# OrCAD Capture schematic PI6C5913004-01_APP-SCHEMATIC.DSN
size B; title: PI6C5913004-01 Application Schematic; rev: 1.0; note: Diodes Inc. Clock IC Application Engineering
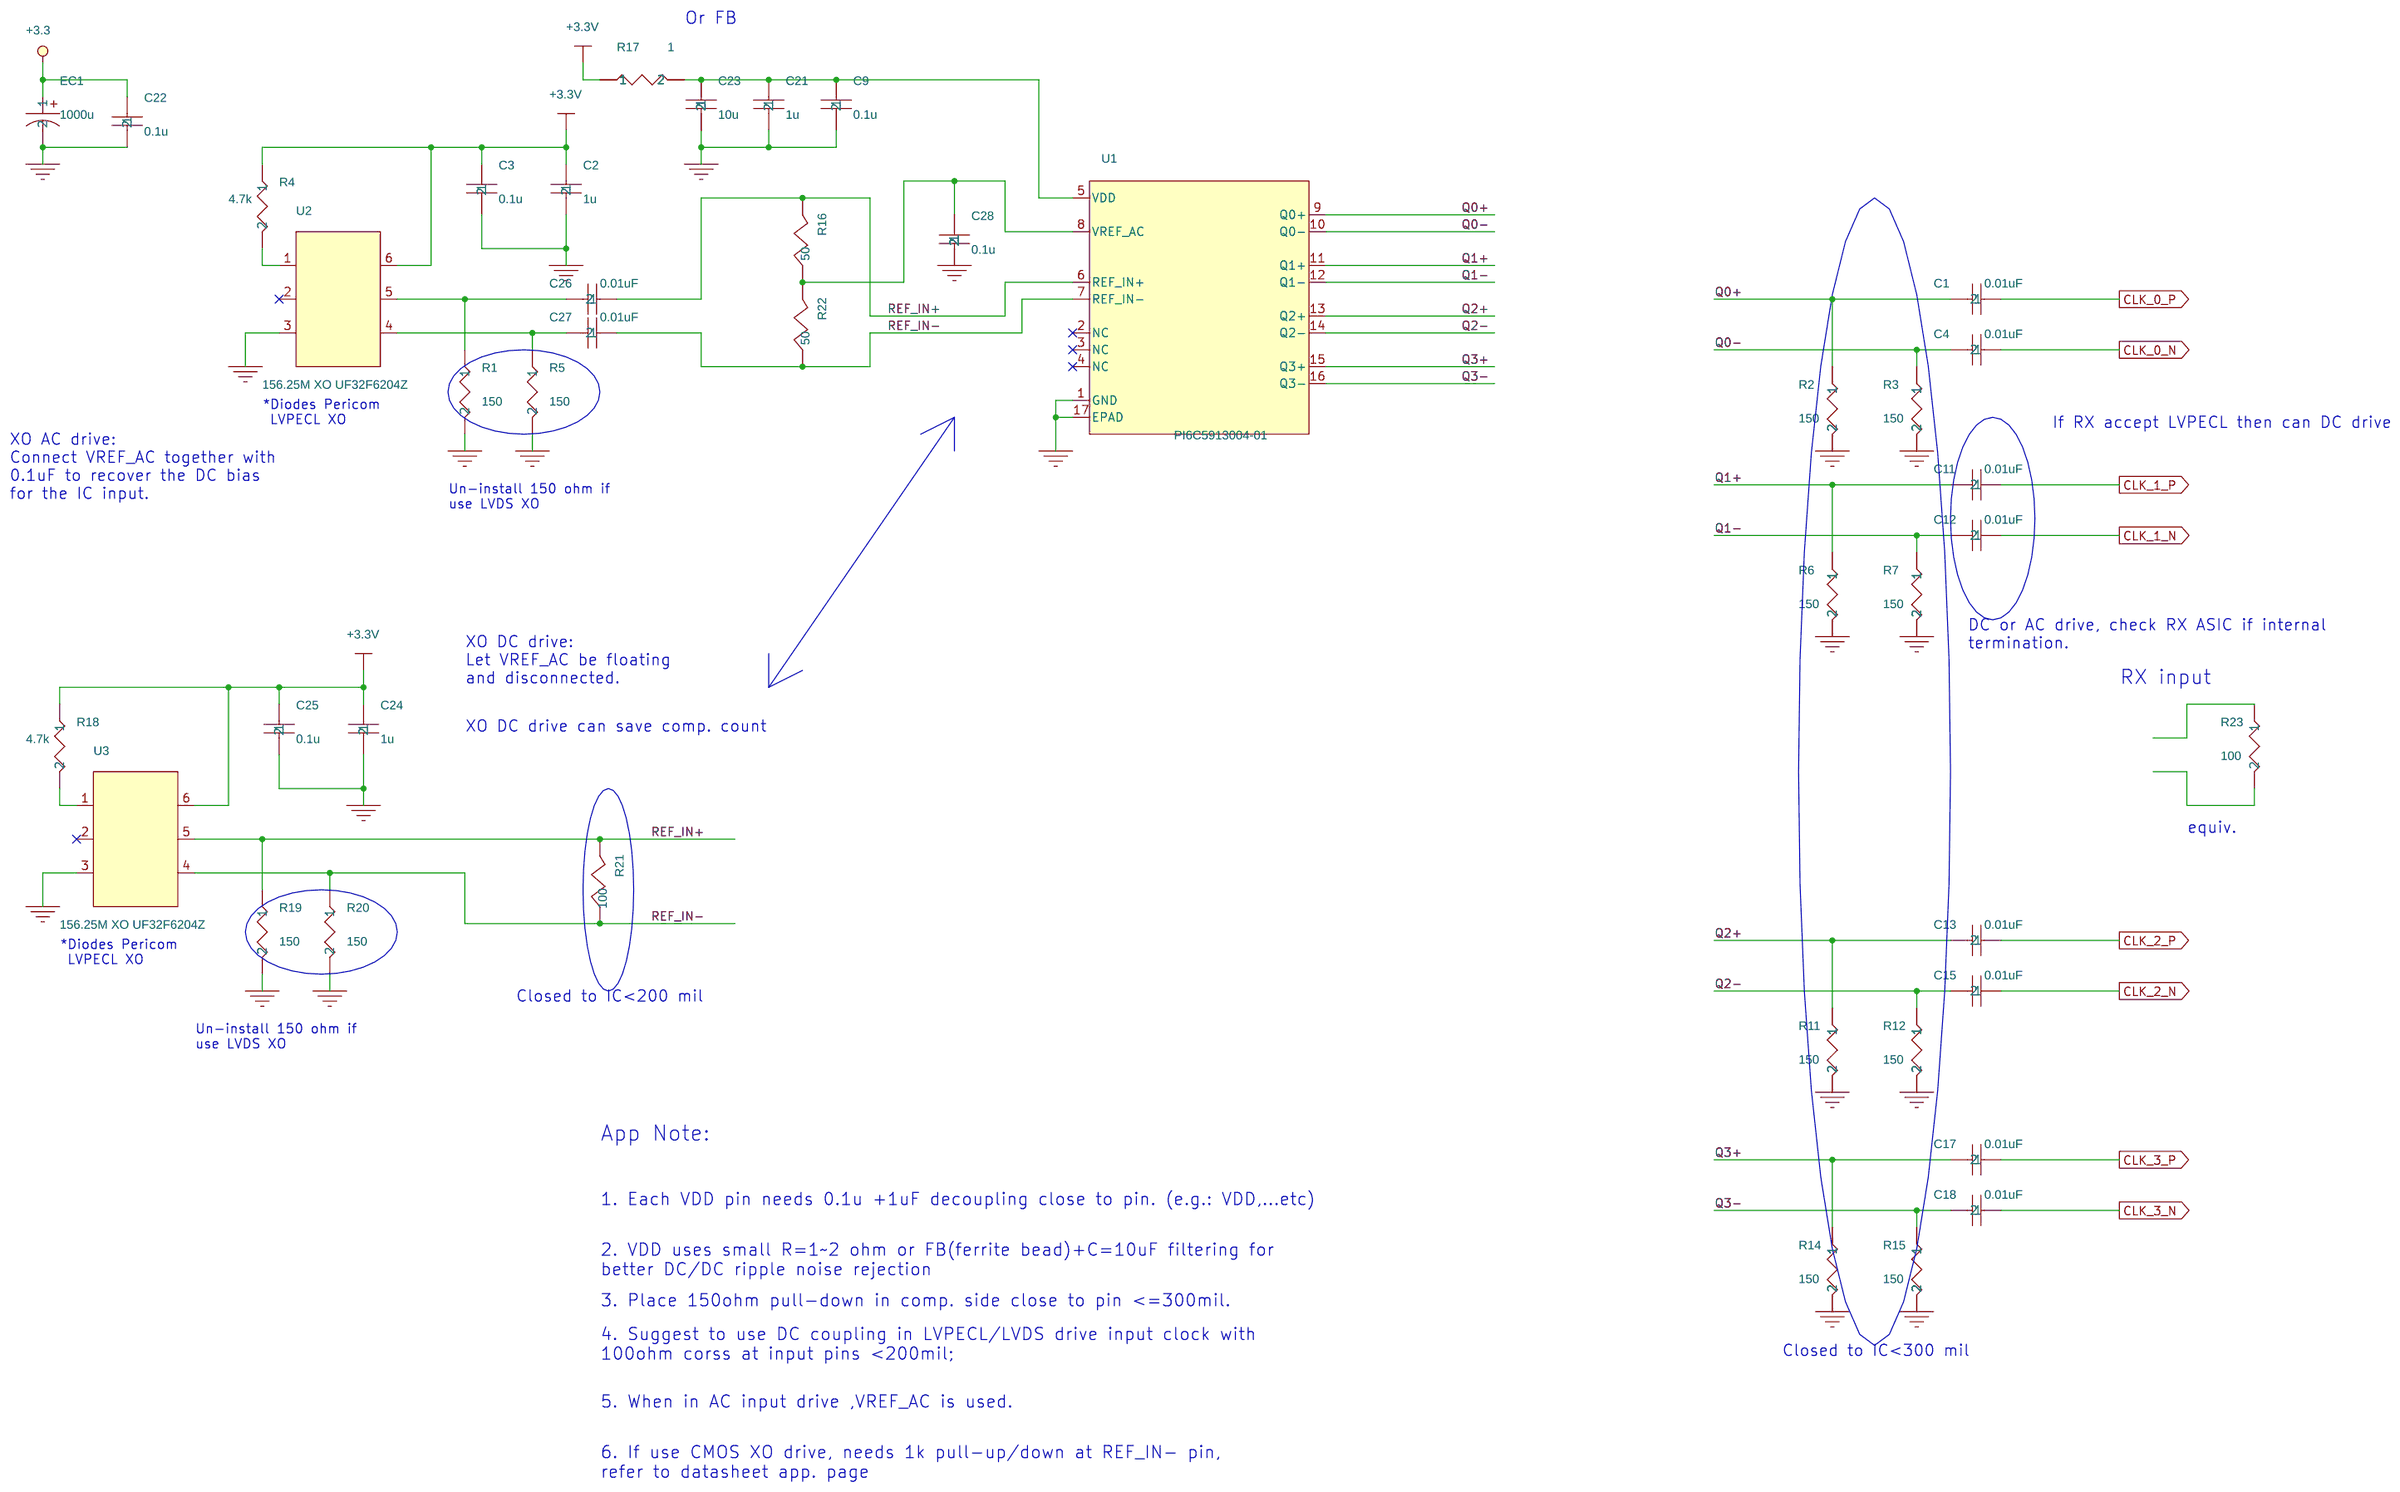
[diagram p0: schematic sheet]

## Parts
C1  0.01uF  [CC_0402]
C2  1u  [CC_0402]
C3  0.1u  [CC_0402]
C4  0.01uF  [CC_0402]
C9  0.1u  [CC_0402]
C11  0.01uF  [CC_0402]
C12  0.01uF  [CC_0402]
C13  0.01uF  [CC_0402]
C15  0.01uF  [CC_0402]
C17  0.01uF  [CC_0402]
C18  0.01uF  [CC_0402]
C21  1u  [CC_0805]
C22  0.1u  [CC_0402]
C23  10u  [CC_0805]
C24  1u  [CC_0402]
C25  0.1u  [CC_0402]
C26  0.01uF  [CC_0402]
C27  0.01uF  [CC_0402]
C28  0.1u  [CC_0402]
EC1  1000u  [CAP1000UF]
R1  150  [R_0402]
R2  150  [R_0402]
R3  150  [R_0402]
R4  4.7k  [R_0402]
R5  150  [R_0402]
R6  150  [R_0402]
R7  150  [R_0402]
R11  150  [R_0402]
R12  150  [R_0402]
R14  150  [R_0402]
R15  150  [R_0402]
R16  50
R17  1  [R_0402]
R18  4.7k  [R_0402]
R19  150  [R_0402]
R20  150  [R_0402]
R21  100
R22  50
R23  100  [R_0402]
U1  PI6C5913004-01
U2  156.25M XO UF32F6204Z  [XO 5X7]
U3  156.25M XO UF32F6204Z  [XO 5X7]

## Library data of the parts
C1 = C_10n_0402_2
C2 = C_0.1u_0402_3
C3 = C_0.1u_0402_2
C4 = C_10n_0402_7
C9 = C_0.1u_0402_1
C11 = C_10n_0402_6
C12 = C_10n_0402_9
C13 = C_10n_0402_8
C15 = C_10n_0402_1
C17 = C_10n_0402_5
C18 = C_10n_0402_4
C21 = C_1.0u_0805_1
C22 = C_0.1u_0402
C23 = C_1.0u_0805
C24 = C_0.1u_0402_6
C25 = C_0.1u_0402_4
C26 = C_10n_0402_3
C27 = C_10n_0402
C28 = C_0.1u_0402_5
EC1 = C_alum_1000u
R1 = R_0402_6
R2 = R_0_7
R3 = R_0_3
R4 = R_0402
R5 = R_0402_4
R6 = R_0_6
R7 = R_0_2
R11 = R_0
R12 = R_0_8
R14 = R_0_5
R15 = R_0_4
R16 R21 R22 = res1
R17 = R_0402_3
R18 = R_0402_5
R19 = R_0402_2
R20 = R_0402_1
R23 = R_0_1
U1 = PI6C4911504-03_6
U2 U3 = XO_5X7

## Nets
+3.3V: C2.1 C3.1 C24.1 C25.1 R4.1 R17.1 R18.1 U2.6 U3.6
GND: C2.2 C3.2 C9.2 C21.2 C22.2 C23.2 C24.2 C25.2 C28.2 EC1.2 R1.2 R2.2 R3.2 R5.2 R6.2 R7.2 R11.2 R12.2 R14.2 R15.2 R19.2 R20.2 U1.1(GND) U1.17(EPAD) U2.3 U3.3
+3.3: C22.1 EC1.1
CLK_0_N: C4.1
CLK_0_P: C1.1
CLK_1_N: C12.1
CLK_1_P: C11.1
CLK_2_N: C15.1
CLK_2_P: C13.1
CLK_3_N: C18.1
CLK_3_P: C17.1
Q0+: C1.2 R2.1 U1.9(Q0+)
Q0-: C4.2 R3.1 U1.10(Q0-)
Q1+: C11.2 R6.1 U1.11(Q1+)
Q1-: C12.2 R7.1 U1.12(Q1-)
Q2+: C13.2 R11.1 U1.13(Q2+)
Q2-: C15.2 R12.1 U1.14(Q2-)
Q3+: C17.2 R14.1 U1.15(Q3+)
Q3-: C18.2 R15.1 U1.16(Q3-)
REF_IN+: C26.1 R16.2 R19.1 R21.2 U1.6(REF_IN+) U3.5
REF_IN-: C27.1 R20.1 R21.1 R22.1 U1.7(REF_IN-) U3.4
N4605837: C9.1 C21.1 C23.1 R17.2 U1.5(VDD)
N4608051: C28.1 R16.1 R22.2 U1.8(VREF_AC)
N4608779: C27.2 R5.1 U2.4
N4608783: C26.2 R1.1 U2.5
N4608823: R4.2 U2.1
N4609914: R18.2 U3.1

Not connected (* = marked no-connect by the designer): R23 1 2; U1 2(NC)* 3(NC)* 4(NC)*; U2 2*; U3 2*

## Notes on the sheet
- Or FB
- *Diodes Pericom
   LVPECL XO
- If RX accept LVPECL then can DC drive
- XO AC drive:
  Connect VREF_AC together with
  0.1uF to recover the DC bias
  for the IC input.
- Un-install 150 ohm if
  use LVDS XO
- XO DC drive:
  Let VREF_AC be floating
  and disconnected.
- DC or AC drive, check RX ASIC if internal
  termination.
- RX input
- XO DC drive can save comp. count
- equiv.
- *Diodes Pericom
   LVPECL XO
- Closed to IC<200 mil
- Un-install 150 ohm if
  use LVDS XO
- App Note:
- 1. Each VDD pin needs 0.1u +1uF decoupling close to pin. (e.g.: VDD,...etc)
- 2. VDD uses small R=1~2 ohm or FB(ferrite bead)+C=10uF filtering for
  better DC/DC ripple noise rejection
- 3. Place 150ohm pull-down in comp. side close to pin <=300mil.
- 4. Suggest to use DC coupling in LVPECL/LVDS drive input clock with
  100ohm corss at input pins <200mil;
- Closed to IC<300 mil
- 5. When in AC input drive ,VREF_AC is used.
- 6. If use CMOS XO drive, needs 1k pull-up/down at REF_IN- pin,
  refer to datasheet app. page
